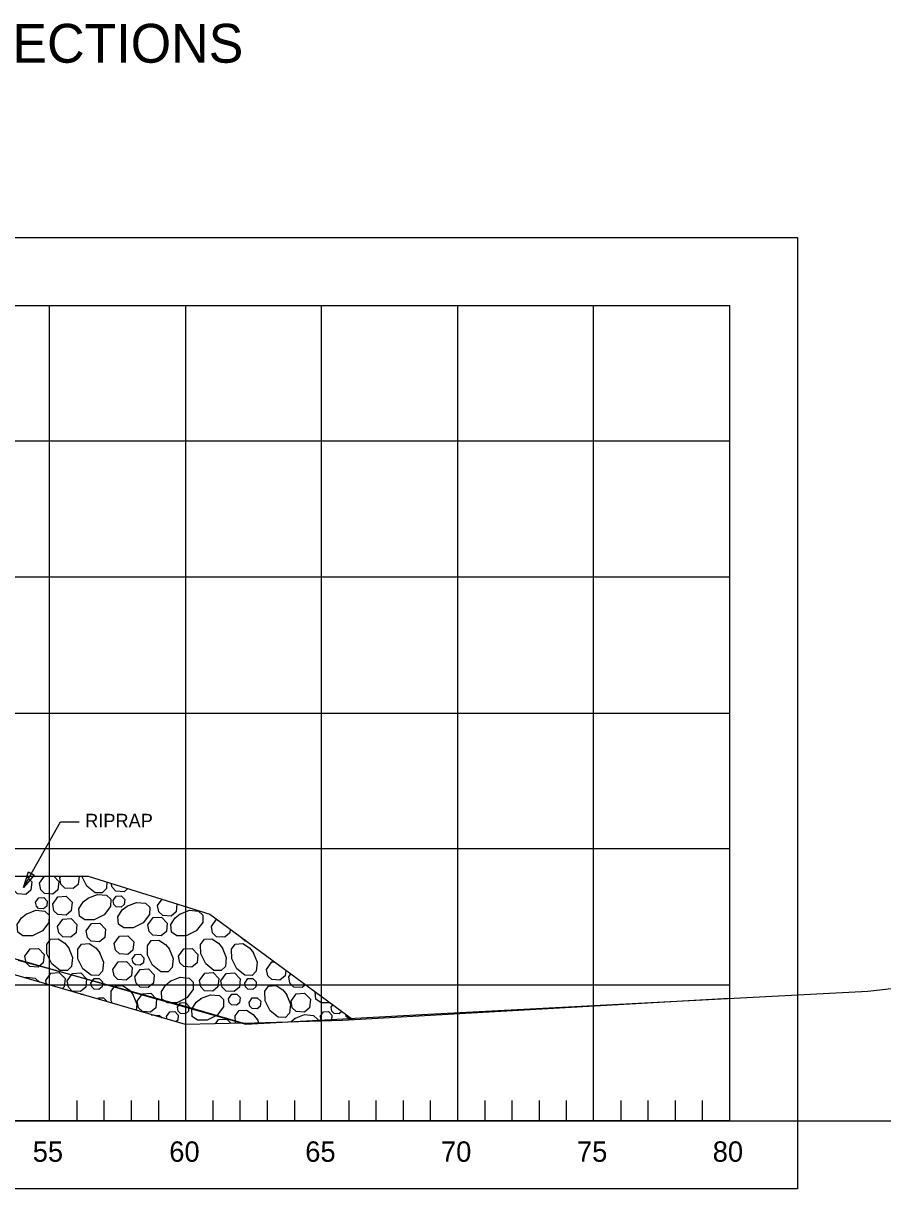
# Model space of a CAD drawing. Extents: x 1578769 to 1579225, y 724002 to 724828.
# Drawn here: x 1578895.27 to 1578926.86, y 724434.97 to 724477.85 of the extents above; entities that cross this region are included whole.
import ezdxf

# ---------------------------------------------------------------- set-up
doc = ezdxf.new("R2010")
doc.units = 0
for name, color, linetype in [('1', 7, 'Continuous'), ('Default', 7, 'Continuous'), ('Old_Level_1', 7, 'Continuous'), ('Old_Level_41', 7, 'Continuous'), ('Old_Level_42', 7, 'Continuous'), ('R_Exist Surface', 7, 'Continuous'), ('R_Rip-Rap', 7, 'Continuous')]:
    doc.layers.add(name, color=color, linetype=linetype)

msp = doc.modelspace()

# ---------------------------------------------------------------- linework, layer by layer
at = {"layer": '1'}
msp.add_lwpolyline([(1578895.267, 724446.052), (1578896.636, 724448.466), (1578897.321, 724448.466)], dxfattribs=at)
msp.add_lwpolyline([(1578895.668, 724446.515), (1578895.267, 724446.052), (1578895.459, 724446.634)], close=True, dxfattribs=at)
at = {"layer": 'Default'}
msp.add_line((1578841.23, 724437.474), (1579141.23, 724437.474), dxfattribs=at)
msp.add_lwpolyline([(1578841.23, 724457.071), (1578842.26, 724457.059), (1578863.33, 724456.943), (1578874.29, 724456.885), (1578876.4, 724454.796), (1578883.17, 724446.782), (1578901.02, 724441.71), (1578903.45, 724441.029), (1578909.92, 724441.377), (1578926.32, 724442.247), (1578964.09, 724446.554), (1578966.7, 724446.865), (1578977.39, 724447.842), (1578995.69, 724449.505), (1578999.6, 724449.841), (1579038.5, 724453.366)], dxfattribs=at)
at = {"layer": 'Old_Level_1'}
for points in [[(1578816.23, 724469.974), (1578923.73, 724469.974), (1578923.73, 724434.974), (1578816.23, 724434.974)], [(1578821.23, 724467.474), (1578921.23, 724467.474), (1578921.23, 724437.474), (1578821.23, 724437.474)]]:
    msp.add_lwpolyline(points, close=True, dxfattribs=at)
at = {"layer": 'Old_Level_41'}
for p, q in [((1578896.23, 724437.474), (1578896.23, 724467.474)), ((1578901.23, 724467.474), (1578901.23, 724437.474)), ((1578906.23, 724437.474), (1578906.23, 724467.474)), ((1578911.23, 724467.474), (1578911.23, 724437.474)), ((1578916.23, 724437.474), (1578916.23, 724467.474))]:
    msp.add_line(p, q, dxfattribs=at)
for points in [[(1578921.23, 724462.474), (1578821.23, 724462.474)], [(1578921.23, 724457.474), (1578821.23, 724457.474)], [(1578821.23, 724452.474), (1578921.23, 724452.474)], [(1578921.23, 724447.474), (1578821.23, 724447.474)], [(1578821.23, 724442.474), (1578921.23, 724442.474)]]:
    msp.add_lwpolyline(points, dxfattribs=at)
at = {"layer": 'Old_Level_42'}
for p, q in [((1578897.23, 724438.224), (1578897.23, 724437.474)), ((1578898.23, 724438.224), (1578898.23, 724437.474)), ((1578899.23, 724438.224), (1578899.23, 724437.474)), ((1578900.23, 724438.224), (1578900.23, 724437.474)), ((1578902.23, 724438.224), (1578902.23, 724437.474)), ((1578903.23, 724438.224), (1578903.23, 724437.474)), ((1578904.23, 724438.224), (1578904.23, 724437.474)), ((1578905.23, 724438.224), (1578905.23, 724437.474)), ((1578907.23, 724438.224), (1578907.23, 724437.474)), ((1578908.23, 724438.224), (1578908.23, 724437.474)), ((1578909.23, 724438.224), (1578909.23, 724437.474)), ((1578910.23, 724438.224), (1578910.23, 724437.474)), ((1578912.23, 724438.224), (1578912.23, 724437.474)), ((1578913.23, 724438.224), (1578913.23, 724437.474)), ((1578914.23, 724438.224), (1578914.23, 724437.474)), ((1578915.23, 724438.224), (1578915.23, 724437.474)), ((1578917.23, 724438.224), (1578917.23, 724437.474)), ((1578918.23, 724438.224), (1578918.23, 724437.474)), ((1578919.23, 724438.224), (1578919.23, 724437.474)), ((1578920.23, 724438.224), (1578920.23, 724437.474))]:
    msp.add_line(p, q, dxfattribs=at)
at = {"layer": 'R_Exist Surface'}
msp.add_lwpolyline([(1578895.079, 724443.387), (1578896.257, 724443.057), (1578901.306, 724441.661), (1578903.355, 724441.069), (1578907.004, 724441.173), (1578921.23, 724441.989)], dxfattribs=at)
at = {"layer": 'R_Rip-Rap'}
for p, q in [((1578879.328, 724446.474), (1578897.646, 724446.474)), ((1578895.857, 724446.21), (1578896.042, 724446.474)), ((1578896.602, 724446.41), (1578896.646, 724446.474)), ((1578897.646, 724446.474), (1578902.123, 724445.08)), ((1578900.204, 724445.399), (1578900.365, 724445.627)), ((1578902.123, 724445.08), (1578907.382, 724441.194)), ((1578901.23, 724441.009), (1578889.685, 724444.377)), ((1578905.022, 724442.77), (1578905.1, 724442.88)), ((1578896.114, 724442.501), (1578896.088, 724442.635)), ((1578906.582, 724441.647), (1578906.646, 724441.738)), ((1578900.553, 724441.206), (1578900.532, 724441.314)), ((1578903.858, 724441.218), (1578903.91, 724441.085)), ((1578905.098, 724441.118), (1578905.257, 724441.245)), ((1578903.355, 724441.069), (1578901.23, 724441.009))]:
    msp.add_line(p, q, dxfattribs=at)
for points in [[(1578895.38, 724446.474), (1578895.578, 724446.268), (1578895.547, 724445.959), (1578895.357, 724445.801), (1578895.055, 724445.823), (1578894.912, 724445.961), (1578894.866, 724446.199)], [(1578896.382, 724446.474), (1578896.569, 724446.28), (1578896.538, 724445.97), (1578896.348, 724445.812), (1578896.046, 724445.834), (1578895.903, 724445.972), (1578895.857, 724446.21)], [(1578897.313, 724446.474), (1578897.283, 724446.17), (1578897.093, 724446.013), (1578896.791, 724446.035), (1578896.648, 724446.173), (1578896.602, 724446.41)], [(1578898.339, 724446.258), (1578898.318, 724446.014), (1578898.169, 724445.857), (1578897.901, 724445.862), (1578897.597, 724446.1), (1578897.413, 724446.468), (1578897.413, 724446.474)], [(1578899.111, 724446.018), (1578898.973, 724445.902), (1578898.67, 724445.924), (1578898.527, 724446.062), (1578898.499, 724446.208)], [(1578895.716, 724445.511), (1578895.831, 724445.675), (1578896.015, 724445.685), (1578896.143, 724445.553), (1578896.125, 724445.367), (1578896.011, 724445.272), (1578895.829, 724445.286), (1578895.744, 724445.368), (1578895.716, 724445.511)], [(1578896.346, 724445.44), (1578896.538, 724445.713), (1578896.844, 724445.731), (1578897.058, 724445.51), (1578897.027, 724445.2), (1578896.837, 724445.043), (1578896.535, 724445.064), (1578896.392, 724445.203), (1578896.346, 724445.44)], [(1578897.635, 724445.659), (1578897.994, 724445.801), (1578898.324, 724445.773), (1578898.481, 724445.623), (1578898.476, 724445.356), (1578898.238, 724445.051), (1578897.87, 724444.867), (1578897.523, 724444.861), (1578897.328, 724445), (1578897.309, 724445.276), (1578897.468, 724445.523), (1578897.649, 724445.668)], [(1578898.568, 724445.574), (1578898.684, 724445.738), (1578898.868, 724445.748), (1578898.996, 724445.616), (1578898.977, 724445.43), (1578898.863, 724445.335), (1578898.682, 724445.349), (1578898.596, 724445.432), (1578898.569, 724445.574)], [(1578899.066, 724445.364), (1578899.425, 724445.506), (1578899.756, 724445.478), (1578899.912, 724445.328), (1578899.907, 724445.061), (1578899.669, 724444.756), (1578899.301, 724444.572), (1578898.955, 724444.566), (1578898.759, 724444.705), (1578898.741, 724444.981), (1578898.899, 724445.228), (1578899.081, 724445.373)], [(1578900.915, 724445.456), (1578900.885, 724445.159), (1578900.696, 724445.001), (1578900.393, 724445.023), (1578900.251, 724445.161), (1578900.204, 724445.399)], [(1578895.365, 724445.073), (1578895.724, 724445.216), (1578896.054, 724445.187), (1578896.211, 724445.038), (1578896.206, 724444.77), (1578895.968, 724444.466), (1578895.6, 724444.282), (1578895.253, 724444.276), (1578895.058, 724444.414), (1578895.04, 724444.691), (1578895.198, 724444.938), (1578895.379, 724445.082)], [(1578899.843, 724444.676), (1578900.035, 724444.949), (1578900.341, 724444.967), (1578900.555, 724444.745), (1578900.524, 724444.436), (1578900.334, 724444.278), (1578900.032, 724444.3), (1578899.889, 724444.438), (1578899.843, 724444.676)], [(1578901.018, 724445.073), (1578901.378, 724445.216), (1578901.708, 724445.187), (1578901.865, 724445.038), (1578901.86, 724444.77), (1578901.621, 724444.466), (1578901.253, 724444.282), (1578900.907, 724444.276), (1578900.711, 724444.414), (1578900.693, 724444.691), (1578900.851, 724444.938), (1578901.033, 724445.082)], [(1578896.526, 724444.622), (1578896.718, 724444.895), (1578897.025, 724444.913), (1578897.238, 724444.692), (1578897.207, 724444.382), (1578897.018, 724444.225), (1578896.715, 724444.246), (1578896.573, 724444.385), (1578896.527, 724444.622)], [(1578897.577, 724444.455), (1578897.769, 724444.728), (1578898.075, 724444.746), (1578898.288, 724444.525), (1578898.258, 724444.215), (1578898.068, 724444.057), (1578897.765, 724444.079), (1578897.623, 724444.217), (1578897.577, 724444.455)], [(1578902.18, 724444.622), (1578902.372, 724444.895), (1578902.372, 724444.896)], [(1578902.875, 724444.524), (1578902.861, 724444.382), (1578902.671, 724444.225), (1578902.369, 724444.246), (1578902.226, 724444.385), (1578902.18, 724444.622)], [(1578896.926, 724443.844), (1578897.069, 724443.484), (1578897.04, 724443.154), (1578896.891, 724442.997), (1578896.623, 724443.002), (1578896.319, 724443.241), (1578896.135, 724443.609), (1578896.129, 724443.955), (1578896.267, 724444.151), (1578896.544, 724444.169), (1578896.791, 724444.011), (1578896.935, 724443.829)], [(1578898.611, 724443.99), (1578898.803, 724444.263), (1578899.11, 724444.281), (1578899.323, 724444.06), (1578899.292, 724443.75), (1578899.103, 724443.593), (1578898.8, 724443.614), (1578898.657, 724443.753), (1578898.611, 724443.99)], [(1578900.627, 724443.797), (1578900.77, 724443.438), (1578900.741, 724443.108), (1578900.592, 724442.951), (1578900.324, 724442.956), (1578900.02, 724443.194), (1578899.836, 724443.562), (1578899.83, 724443.909), (1578899.969, 724444.104), (1578900.245, 724444.122), (1578900.492, 724443.964), (1578900.637, 724443.783)], [(1578902.58, 724443.844), (1578902.722, 724443.484), (1578902.693, 724443.154), (1578902.544, 724442.997), (1578902.276, 724443.002), (1578901.972, 724443.241), (1578901.788, 724443.609), (1578901.782, 724443.955), (1578901.921, 724444.151), (1578902.197, 724444.169), (1578902.444, 724444.011), (1578902.589, 724443.829)], [(1578903.484, 724444.074), (1578903.419, 724444.079), (1578903.276, 724444.217), (1578903.274, 724444.229)], [(1578895.319, 724443.525), (1578895.511, 724443.799), (1578895.818, 724443.816), (1578896.031, 724443.595), (1578896, 724443.285), (1578895.811, 724443.128), (1578895.508, 724443.15), (1578895.365, 724443.288), (1578895.319, 724443.525)], [(1578898.065, 724443.669), (1578898.207, 724443.31), (1578898.179, 724442.98), (1578898.03, 724442.823), (1578897.762, 724442.828), (1578897.457, 724443.066), (1578897.274, 724443.434), (1578897.267, 724443.781), (1578897.406, 724443.976), (1578897.682, 724443.995), (1578897.929, 724443.836), (1578898.074, 724443.655)], [(1578900.972, 724443.525), (1578901.164, 724443.799), (1578901.471, 724443.816), (1578901.684, 724443.595), (1578901.654, 724443.285), (1578901.464, 724443.128), (1578901.161, 724443.15), (1578901.019, 724443.288), (1578900.973, 724443.525)], [(1578903.718, 724443.669), (1578903.861, 724443.31), (1578903.832, 724442.98), (1578903.683, 724442.823), (1578903.415, 724442.828), (1578903.111, 724443.066), (1578902.927, 724443.434), (1578902.921, 724443.781), (1578903.06, 724443.976), (1578903.336, 724443.995), (1578903.583, 724443.836), (1578903.728, 724443.655)], [(1578898.557, 724443.041), (1578898.749, 724443.315), (1578899.056, 724443.332), (1578899.269, 724443.111), (1578899.238, 724442.801), (1578899.049, 724442.644), (1578898.746, 724442.666), (1578898.604, 724442.804), (1578898.557, 724443.041)], [(1578899.271, 724443.43), (1578899.386, 724443.594), (1578899.57, 724443.605), (1578899.698, 724443.472), (1578899.68, 724443.286), (1578899.566, 724443.192), (1578899.384, 724443.205), (1578899.299, 724443.288), (1578899.271, 724443.43)], [(1578904.211, 724443.041), (1578904.403, 724443.315), (1578904.504, 724443.32)], [(1578896.088, 724442.635), (1578896.28, 724442.908), (1578896.586, 724442.925), (1578896.8, 724442.704), (1578896.769, 724442.395), (1578896.693, 724442.332)], [(1578896.878, 724442.623), (1578897.07, 724442.896), (1578897.377, 724442.914), (1578897.59, 724442.693), (1578897.559, 724442.383), (1578897.369, 724442.225), (1578897.067, 724442.247), (1578896.924, 724442.386), (1578896.878, 724442.623)], [(1578899.369, 724442.77), (1578899.561, 724443.043), (1578899.868, 724443.061), (1578900.081, 724442.84), (1578900.05, 724442.53), (1578899.861, 724442.372), (1578899.558, 724442.394), (1578899.415, 724442.533), (1578899.369, 724442.77)], [(1578901.741, 724442.635), (1578901.933, 724442.908), (1578902.24, 724442.925), (1578902.453, 724442.704), (1578902.422, 724442.395), (1578902.233, 724442.237), (1578901.93, 724442.259), (1578901.788, 724442.397), (1578901.741, 724442.635)], [(1578902.531, 724442.623), (1578902.723, 724442.896), (1578903.03, 724442.914), (1578903.243, 724442.693), (1578903.212, 724442.383), (1578903.023, 724442.225), (1578902.72, 724442.247), (1578902.578, 724442.386), (1578902.531, 724442.623)], [(1578904.913, 724443.018), (1578904.892, 724442.801), (1578904.702, 724442.644), (1578904.399, 724442.666), (1578904.257, 724442.804), (1578904.211, 724443.041)], [(1578895.324, 724442.732), (1578895.376, 724442.752), (1578895.706, 724442.724), (1578895.862, 724442.575)], [(1578897.752, 724442.539), (1578897.867, 724442.703), (1578898.051, 724442.713), (1578898.179, 724442.58), (1578898.16, 724442.395), (1578898.047, 724442.3), (1578897.865, 724442.313), (1578897.78, 724442.396), (1578897.752, 724442.539)], [(1578898.549, 724441.791), (1578898.5, 724441.889), (1578898.494, 724442.236), (1578898.632, 724442.431), (1578898.909, 724442.449), (1578899.156, 724442.291), (1578899.3, 724442.109)], [(1578900.67, 724442.61), (1578901.029, 724442.752), (1578901.359, 724442.724), (1578901.516, 724442.574), (1578901.511, 724442.307), (1578901.273, 724442.002), (1578900.905, 724441.818), (1578900.558, 724441.812), (1578900.363, 724441.951), (1578900.344, 724442.227), (1578900.503, 724442.474), (1578900.684, 724442.619)], [(1578903.405, 724442.539), (1578903.52, 724442.703), (1578903.705, 724442.713), (1578903.832, 724442.58), (1578903.814, 724442.395), (1578903.7, 724442.3), (1578903.519, 724442.313), (1578903.433, 724442.396), (1578903.405, 724442.539)], [(1578904.944, 724442.124), (1578905.087, 724441.765), (1578905.058, 724441.435), (1578904.909, 724441.278), (1578904.641, 724441.283), (1578904.337, 724441.521), (1578904.153, 724441.889), (1578904.147, 724442.236), (1578904.286, 724442.431), (1578904.562, 724442.449), (1578904.809, 724442.291), (1578904.954, 724442.109)], [(1578905.643, 724442.479), (1578905.514, 724442.372), (1578905.211, 724442.394), (1578905.069, 724442.533), (1578905.022, 724442.77)], [(1578897.379, 724442.132), (1578897.457, 724442.137), (1578897.493, 724442.099)], [(1578898.001, 724441.951), (1578898.029, 724441.991), (1578898.213, 724442.002), (1578898.341, 724441.869), (1578898.339, 724441.852)], [(1578899.291, 724442.124), (1578899.434, 724441.765), (1578899.414, 724441.539)], [(1578899.454, 724441.871), (1578899.646, 724442.144), (1578899.953, 724442.162), (1578900.166, 724441.941), (1578900.135, 724441.631), (1578899.946, 724441.474), (1578899.643, 724441.495), (1578899.501, 724441.634), (1578899.454, 724441.871)], [(1578901.784, 724441.968), (1578902.144, 724442.11), (1578902.474, 724442.082), (1578902.631, 724441.933), (1578902.626, 724441.665), (1578902.388, 724441.36), (1578902.02, 724441.176), (1578901.673, 724441.17), (1578901.478, 724441.309), (1578901.459, 724441.585), (1578901.618, 724441.832), (1578901.799, 724441.977)], [(1578902.811, 724441.962), (1578902.926, 724442.126), (1578903.11, 724442.137), (1578903.238, 724442.004), (1578903.219, 724441.818), (1578903.106, 724441.724), (1578902.924, 724441.737), (1578902.839, 724441.82), (1578902.811, 724441.962)], [(1578903.567, 724441.827), (1578903.683, 724441.991), (1578903.867, 724442.002), (1578903.995, 724441.869), (1578903.976, 724441.683), (1578903.862, 724441.589), (1578903.681, 724441.602), (1578903.595, 724441.685), (1578903.567, 724441.827)], [(1578905.108, 724441.871), (1578905.3, 724442.144), (1578905.607, 724442.162), (1578905.82, 724441.941), (1578905.789, 724441.631), (1578905.599, 724441.474), (1578905.297, 724441.495), (1578905.154, 724441.634), (1578905.108, 724441.871)], [(1578906.538, 724441.818), (1578906.212, 724441.812), (1578906.016, 724441.951), (1578905.999, 724442.216)], [(1578900.928, 724441.647), (1578901.044, 724441.811), (1578901.228, 724441.821), (1578901.355, 724441.689), (1578901.337, 724441.503), (1578901.223, 724441.408), (1578901.042, 724441.422), (1578900.956, 724441.504), (1578900.928, 724441.647)], [(1578903.065, 724441.061), (1578903.06, 724441.329), (1578903.199, 724441.524), (1578903.475, 724441.543), (1578903.722, 724441.385), (1578903.867, 724441.203)], [(1578906.978, 724441.493), (1578906.877, 724441.408), (1578906.695, 724441.422), (1578906.61, 724441.504), (1578906.582, 724441.647)], [(1578899.97, 724441.376), (1578900.278, 724441.35), (1578900.374, 724441.259)], [(1578900.532, 724441.314), (1578900.647, 724441.478), (1578900.831, 724441.488), (1578900.959, 724441.356), (1578900.941, 724441.17), (1578900.873, 724441.113)], [(1578902.336, 724441.04), (1578902.447, 724441.198), (1578902.754, 724441.216), (1578902.908, 724441.056)], [(1578904.631, 724441.105), (1578904.633, 724441.105), (1578904.633, 724441.105)], [(1578905.242, 724441.236), (1578905.601, 724441.378), (1578905.931, 724441.35), (1578906.088, 724441.201), (1578906.087, 724441.147)], [(1578906.185, 724441.314), (1578906.301, 724441.478), (1578906.485, 724441.488), (1578906.613, 724441.356), (1578906.594, 724441.17), (1578906.583, 724441.161)], [(1578906.234, 724441.151), (1578906.213, 724441.171), (1578906.186, 724441.314)], [(1578907.299, 724441.19), (1578907.131, 724441.309), (1578907.126, 724441.383)]]:
    msp.add_lwpolyline(points, dxfattribs=at)

# ---------------------------------------------------------------- texts
at = {"layer": '1'}
for s, height, p in [('RIPRAP', 0.5, (1578897.538, 724448.266)), ('55', 0.75, (1578895.611, 724435.964)), ('60', 0.75, (1578900.632, 724435.964)), ('65', 0.75, (1578905.632, 724435.964)), ('70', 0.75, (1578910.623, 724435.964)), ('75', 0.75, (1578915.623, 724435.964)), ('80', 0.75, (1578920.614, 724435.964))]:
    msp.add_text(s, height=height, dxfattribs=at).set_placement(p)
at = {"layer": 'Old_Level_1'}
msp.add_text('TYPICAL RIFFLE, POOL, AND BANKFULL BENCH CROSS SECTIONS', height=1.42857, dxfattribs=at).set_placement((1578841.574, 724476.402))

doc.saveas('drawing.dxf')
